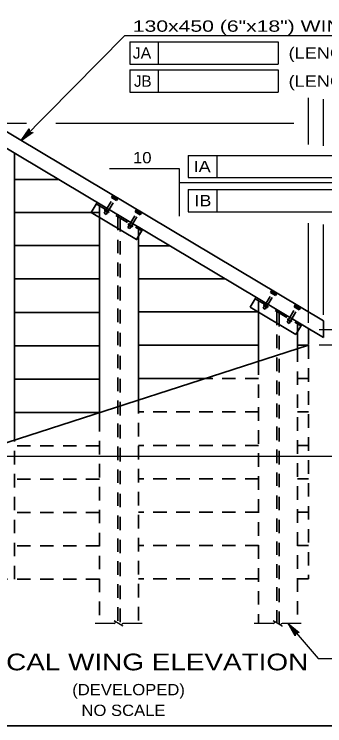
# Model space of a CAD drawing. Extents: x -6.4 to 73.1, y -66 to 0.
# Drawn here: x 50.97 to 54.26, y -43.25 to -35.69 of the extents above; entities that cross this region are included whole.
import ezdxf
from ezdxf.enums import TextEntityAlignment as Align

# ---------------------------------------------------------------- set-up
doc = ezdxf.new("R2010")
doc.units = 0
doc.header["$LTSCALE"] = 0.048
doc.linetypes.add('MEDIUM_DASHED', pattern=[4.5, 3, -1.5])
for name, color, linetype, lineweight in [('1', 7, 'Continuous', 13), ('3', 7, 'Continuous', 35), ('4', 7, 'Continuous', 25), ('5', 7, 'Continuous', 25), ('8', 7, 'Continuous', 25)]:
    doc.layers.add(name, color=color, linetype=linetype, lineweight=lineweight)

msp = doc.modelspace()

# ---------------------------------------------------------------- hatches: boundary and pattern name
at = {"layer": '4'}
for points in [[(51.13325, -36.96742), (51.10633, -36.94083), (51.04017, -37.03475)], [(53.94975, -42.28008), (53.97833, -42.25533), (53.88992, -42.18183)]]:
    msp.add_hatch(color=256, dxfattribs=at).paths.add_polyline_path(points)

# ---------------------------------------------------------------- linework, layer by layer
at = {"layer": '1', "lineweight": 35}
msp.add_lwpolyline([(35.75, -43.25), (67.25, -43.25), (67.25, -22.75), (35.75, -22.75)], close=True, dxfattribs=at)
at = {"layer": '3'}
for p, q in [((50.73242, -36.85133), (54.24933, -38.94825)), ((50.73242, -37.0285), (54.24933, -39.12542)), ((50.96758, -40.21458), (50.96758, -37.16875)), ((51.43492, -37.44733), (50.96758, -37.44733)), ((51.78183, -37.79742), (51.84483, -37.69175)), ((51.78433, -37.79892), (50.96758, -37.79892)), ((51.87142, -37.85083), (51.87142, -39.97992)), ((52.28483, -38.05383), (52.28483, -39.79033)), ((51.87142, -38.1505), (50.96758, -38.1505)), ((52.61533, -38.15117), (52.28483, -38.15117)), ((52.28483, -38.40183), (52.28483, -38.58925)), ((51.87142, -38.50483), (50.96758, -38.50483)), ((53.20508, -38.50275), (52.28483, -38.50275)), ((53.47225, -38.80533), (53.53525, -38.69967)), ((53.47225, -38.80533), (53.95617, -39.09383)), ((51.87142, -38.85917), (50.96758, -38.85917)), ((53.56183, -38.85433), (52.28483, -38.85433)), ((53.56183, -38.85875), (53.56183, -39.37975)), ((53.95617, -39.09383), (54.01917, -38.98817)), ((54.24933, -38.94825), (54.24933, -39.12542)), ((53.97525, -39.06175), (53.97525, -39.24475)), ((54.09333, -39.03242), (54.09333, -39.20142)), ((54.09333, -39.20867), (50.46133, -40.37758)), ((51.87142, -39.2135), (50.96758, -39.2135)), ((53.56183, -39.20867), (52.28483, -39.20867)), ((54.09333, -39.20867), (53.97525, -39.20867)), ((51.87142, -39.56783), (50.96758, -39.56783)), ((52.99242, -39.563), (52.28483, -39.563)), ((51.87142, -39.92217), (50.96758, -39.92217))]:
    msp.add_line(p, q, dxfattribs=at)
at = {"layer": '3', "linetype": 'MEDIUM_DASHED'}
for p, q in [((51.99733, -37.63892), (52.01192, -37.61417)), ((52.00525, -37.64367), (52.01175, -37.63283)), ((52.01808, -37.632), (52.04692, -37.649)), ((51.92067, -37.806), (52.01367, -37.64858)), ((51.94192, -37.81842), (52.03492, -37.66108)), ((52.05125, -37.67075), (51.99733, -37.63892)), ((52.02075, -37.63833), (52.01442, -37.649)), ((52.03975, -37.64942), (52.03342, -37.66025)), ((52.04333, -37.66608), (52.04958, -37.65517)), ((52.05125, -37.67075), (52.06583, -37.64608)), ((51.93383, -37.76467), (51.92742, -37.7755)), ((51.92983, -37.7815), (51.95867, -37.79842)), ((51.93658, -37.78083), (51.943, -37.77)), ((51.95558, -37.79208), (51.96183, -37.78125)), ((52.24933, -37.79192), (52.26392, -37.76725)), ((51.94192, -37.81842), (51.92067, -37.806)), ((51.97183, -37.787), (51.96533, -37.79783)), ((52.17392, -37.95683), (52.26567, -37.80167)), ((52.19517, -37.96933), (52.28692, -37.81417)), ((52.30333, -37.82383), (52.24933, -37.79192)), ((52.25725, -37.79675), (52.26375, -37.78583)), ((52.27283, -37.79142), (52.26642, -37.802)), ((52.27008, -37.785), (52.29892, -37.80208)), ((52.29183, -37.8025), (52.28542, -37.81325)), ((52.29533, -37.81908), (52.30158, -37.80817)), ((52.30333, -37.82383), (52.31792, -37.79917)), ((52.18708, -37.91558), (52.18067, -37.92642)), ((52.18308, -37.93233), (52.212, -37.94933)), ((52.18983, -37.93175), (52.19625, -37.92092)), ((52.20883, -37.94292), (52.21517, -37.93217)), ((52.19517, -37.96933), (52.17392, -37.95683)), ((52.22517, -37.93783), (52.21858, -37.94875)), ((53.61108, -38.81392), (53.70408, -38.6565)), ((53.63233, -38.82633), (53.72533, -38.669)), ((53.68775, -38.64683), (53.70233, -38.62208)), ((53.74167, -38.67867), (53.68775, -38.64683)), ((53.69567, -38.65158), (53.70217, -38.64075)), ((53.71117, -38.64625), (53.70483, -38.65692)), ((53.7085, -38.63992), (53.73733, -38.65692)), ((53.73017, -38.65733), (53.72383, -38.66817)), ((53.73375, -38.674), (53.74, -38.66308)), ((53.74167, -38.67867), (53.75625, -38.654)), ((53.63233, -38.82633), (53.61108, -38.81392)), ((53.62425, -38.77258), (53.61783, -38.78342)), ((53.62025, -38.78942), (53.64908, -38.80633)), ((53.627, -38.78875), (53.63342, -38.77792)), ((53.646, -38.8), (53.65225, -38.78917)), ((53.66225, -38.79492), (53.65575, -38.80575)), ((53.86433, -38.96475), (53.95608, -38.80958)), ((53.88558, -38.97725), (53.97733, -38.82208)), ((53.93975, -38.79983), (53.95433, -38.77517)), ((53.99375, -38.83175), (53.93975, -38.79983)), ((53.94767, -38.80467), (53.95417, -38.79375)), ((53.96325, -38.79933), (53.95683, -38.80992)), ((53.9605, -38.79292), (53.98933, -38.81)), ((53.98225, -38.81042), (53.97583, -38.82117)), ((53.98575, -38.827), (53.992, -38.81608)), ((53.99375, -38.83175), (54.00833, -38.80708)), ((53.88558, -38.97725), (53.86433, -38.96475)), ((53.8775, -38.9235), (53.87108, -38.93433)), ((53.8735, -38.94025), (53.90242, -38.95725)), ((53.88025, -38.93967), (53.88667, -38.92883)), ((53.89925, -38.95083), (53.90558, -38.94008)), ((53.91558, -38.94575), (53.909, -38.95667)), ((54.09333, -39.20867), (54.09333, -41.689)), ((53.97525, -39.242), (53.97525, -42.14725)), ((53.56183, -39.37975), (53.56183, -42.15833)), ((53.56183, -39.563), (52.99242, -39.563)), ((54.09333, -39.563), (53.97525, -39.563)), ((52.28483, -39.79033), (52.28483, -42.14725)), ((53.56183, -39.91733), (52.28483, -39.91733)), ((54.09333, -39.91733), (53.97525, -39.91733)), ((51.87142, -39.97992), (51.87142, -42.15833)), ((50.96758, -41.69383), (50.96758, -40.21458)), ((51.87142, -40.2765), (50.96758, -40.2765)), ((53.56183, -40.27167), (52.28483, -40.27167)), ((54.09333, -40.27167), (53.97525, -40.27167)), ((51.87142, -40.63083), (50.96758, -40.63083)), ((53.56183, -40.626), (52.28483, -40.626)), ((54.09333, -40.626), (53.97525, -40.626)), ((51.87142, -40.98517), (50.96758, -40.98517)), ((53.56183, -40.98033), (52.28483, -40.98033)), ((54.09333, -40.98033), (53.97525, -40.98033)), ((53.56183, -41.33467), (52.28483, -41.33467)), ((54.09333, -41.33467), (53.97525, -41.33467)), ((51.87142, -41.3395), (50.96758, -41.3395)), ((51.87142, -41.69383), (50.58367, -41.69383)), ((53.56183, -41.689), (52.28483, -41.689)), ((54.09333, -41.689), (53.97525, -41.689))]:
    msp.add_line(p, q, dxfattribs=at)
at = {"layer": '3'}
msp.add_lwpolyline([(51.78183, -37.79742), (52.26575, -38.08592), (52.32875, -37.98025)], dxfattribs=at)
at = {"layer": '3', "linetype": 'MEDIUM_DASHED'}
for centre, radius, start, end in [((52.01543, -37.6369), 0.00557, 346.84976, 131.94615), ((52.02341, -37.65552), 0.01754, 20.44796, 98.34796), ((52.04362, -37.65422), 0.00613, 61.22502, 128.11101), ((52.04362, -37.65422), 0.00613, 350.6849, 61.22502), ((51.93285, -37.77677), 0.00557, 166.9183, 312.01468), ((51.95301, -37.77477), 0.01754, 200.51649, 278.41649), ((52.26749, -37.78995), 0.00557, 346.84976, 131.94615), ((51.96162, -37.7931), 0.00613, 170.75344, 237.63943), ((51.96162, -37.7931), 0.00613, 237.63943, 308.17954), ((52.27546, -37.80857), 0.01754, 20.44796, 98.34796), ((52.29567, -37.80726), 0.00613, 61.22502, 128.11101), ((52.29567, -37.80726), 0.00613, 350.6849, 61.22502), ((52.18615, -37.92771), 0.00557, 166.9183, 312.01468), ((52.2063, -37.9257), 0.01754, 200.51649, 278.41649), ((52.21492, -37.94403), 0.00613, 170.75344, 237.63943), ((52.21492, -37.94403), 0.00613, 237.63943, 308.17954), ((53.70585, -38.64482), 0.00557, 346.84976, 131.94615), ((53.71382, -38.66344), 0.01754, 20.44796, 98.34796), ((53.73403, -38.66213), 0.00613, 61.22502, 128.11101), ((53.73403, -38.66213), 0.00613, 350.6849, 61.22502), ((53.62327, -38.78469), 0.00557, 166.9183, 312.01468), ((53.64342, -38.78268), 0.01754, 200.51649, 278.41649), ((53.65203, -38.80101), 0.00613, 170.75344, 237.63943), ((53.65203, -38.80101), 0.00613, 237.63943, 308.17954), ((53.9579, -38.79787), 0.00557, 346.84976, 131.94615), ((53.96588, -38.81649), 0.01754, 20.44796, 98.34796), ((53.98609, -38.81518), 0.00613, 61.22502, 128.11101), ((53.98609, -38.81518), 0.00613, 350.6849, 61.22502), ((53.87657, -38.93562), 0.00557, 166.9183, 312.01468), ((53.89672, -38.93362), 0.01754, 200.51649, 278.41649), ((53.90533, -38.95195), 0.00613, 170.75344, 237.63943), ((53.90533, -38.95195), 0.00613, 237.63943, 308.17954)]:
    msp.add_arc(centre, radius, start, end, dxfattribs=at)
at = {"layer": '4'}
for p, q in [((51.04008, -37.03483), (52.14075, -35.92042)), ((52.14075, -35.92042), (55.88817, -35.92042)), ((52.19292, -35.98667), (53.76775, -35.98667)), ((52.19292, -35.98667), (52.19292, -36.22292)), ((52.49542, -35.98667), (52.49542, -36.22292)), ((53.76775, -35.98667), (53.76775, -36.22292)), ((52.19292, -36.22292), (53.76775, -36.22292)), ((52.19292, -36.28525), (53.76775, -36.28525)), ((52.19292, -36.28525), (52.19292, -36.52142)), ((52.49542, -36.28525), (52.49542, -36.52142)), ((53.76775, -36.28525), (53.76775, -36.52142)), ((52.19292, -36.52142), (53.76775, -36.52142)), ((54.09333, -37.07767), (54.09333, -36.58208)), ((54.24933, -37.09067), (54.24933, -36.59508)), ((50.85417, -36.85125), (51.094, -36.85125)), ((51.40792, -36.85125), (53.93633, -36.85125)), ((52.81467, -37.19217), (54.3895, -37.19217)), ((52.81467, -37.19217), (52.81467, -37.42842)), ((53.11717, -37.19217), (53.11717, -37.42842)), ((52.72075, -37.33667), (51.97742, -37.33667)), ((52.72075, -37.838), (52.72075, -37.33667)), ((52.81467, -37.42842), (54.3895, -37.42842)), ((55.71433, -37.48275), (52.72075, -37.48275)), ((52.81467, -37.55467), (54.3895, -37.55467)), ((52.81467, -37.55467), (52.81467, -37.79092)), ((53.11717, -37.55467), (53.11717, -37.79092)), ((52.81467, -37.79092), (54.3895, -37.79092)), ((54.09333, -38.97092), (54.09333, -37.91233)), ((54.24933, -38.88475), (54.24933, -37.92542)), ((54.20642, -39.04125), (58.26442, -39.04125)), ((54.53533, -39.20867), (54.20392, -39.20867)), ((54.53533, -40.39192), (50.71225, -40.39192)), ((53.87425, -42.16367), (54.19408, -42.53425)), ((54.19408, -42.53425), (57.859, -42.53425))]:
    msp.add_line(p, q, dxfattribs=at)
at = {"layer": '4', "lineweight": 35}
msp.add_line((50.96758, -37.64), (50.96758, -39.64308), dxfattribs=at)
at = {"layer": '4'}
for points in [[(51.04008, -37.03483), (51.125, -36.90908), (51.12258, -36.92283), (51.1255, -36.93408), (51.13142, -36.94233), (51.13975, -36.94817), (51.151, -36.951), (51.16475, -36.94842), (51.04008, -37.03483), (51.151, -36.951), (51.13975, -36.94817), (51.04008, -37.03483), (51.13142, -36.94233), (51.1255, -36.93408), (51.04008, -37.03483), (51.12258, -36.92283)], [(53.87425, -42.16367), (53.99283, -42.25833), (53.97933, -42.25483), (53.96792, -42.25683), (53.95917, -42.26208), (53.95275, -42.26992), (53.949, -42.28092), (53.9505, -42.29483), (53.87425, -42.16367), (53.949, -42.28092), (53.95275, -42.26992), (53.87425, -42.16367), (53.95917, -42.26208), (53.96792, -42.25683), (53.87425, -42.16367), (53.97933, -42.25483)]]:
    msp.add_lwpolyline(points, dxfattribs=at)
for points in [[(51.13325, -36.96742), (51.10633, -36.94083), (51.04017, -37.03475)], [(53.94975, -42.28008), (53.97833, -42.25533), (53.88992, -42.18183)]]:
    msp.add_lwpolyline(points, close=True, dxfattribs=at)
at = {"layer": '8', "linetype": 'MEDIUM_DASHED', "lineweight": 35}
for p, q in [((51.83617, -37.70633), (52.32008, -37.99475)), ((51.87142, -37.72733), (51.87142, -37.85083)), ((51.87142, -37.79892), (51.78433, -37.79892)), ((52.06633, -37.8435), (52.06633, -42.159)), ((52.08992, -37.85758), (52.08992, -42.17383)), ((52.28483, -37.97375), (52.28483, -38.05383)), ((53.52658, -38.71425), (54.0105, -39.00267)), ((53.56183, -38.73525), (53.56183, -38.85875)), ((53.75675, -38.85142), (53.75675, -42.159)), ((53.78033, -38.8655), (53.78033, -42.17383)), ((53.97525, -38.98167), (53.97525, -39.06175))]:
    msp.add_line(p, q, dxfattribs=at)
at = {"layer": '8'}
for p, q in [((52.02758, -42.16367), (51.82367, -42.16367)), ((52.32492, -42.16367), (52.12083, -42.16367)), ((53.71808, -42.16367), (53.51408, -42.16367)), ((54.01533, -42.16367), (53.81133, -42.16367))]:
    msp.add_line(p, q, dxfattribs=at)
for points in [[(52.114, -42.18908), (52.11983, -42.19267), (52.02742, -42.13458), (52.03358, -42.1385)], [(53.8045, -42.18908), (53.81025, -42.19267), (53.71792, -42.13458), (53.72408, -42.1385)]]:
    msp.add_lwpolyline(points, dxfattribs=at)
for centre, start, end in [((52.02637, -42.14998), 275.32859, 57.86724), ((52.12088, -42.1772), 90, 240), ((53.71682, -42.14998), 275.32859, 57.86724), ((53.81133, -42.1772), 90, 240)]:
    msp.add_arc(centre, 0.01364, start, end, dxfattribs=at)

# ---------------------------------------------------------------- texts
at = {"layer": '4'}
for s, height, width, p in [('JA', 0.12, 1.05, (52.32258, -36.16483)), ('TYPICAL WING ELEVATION', 0.1772, 1.25, (52.15475, -42.66108)), ('(DEVELOPED)', 0.12, 1.1, (52.17996, -42.92617)), ('NO SCALE', 0.12, 1.1, (52.12588, -43.14592))]:
    msp.add_text(s, height=height, dxfattribs=dict(at, width=width)).set_placement(p, align=Align.CENTER)
for s, width, p in [('(LENGTH) WINGWALL A', 1.2, (53.88042, -36.16483)), ('(LENGTH) WINGWALL B', 1.2, (53.88042, -36.46342)), ('10', 1.1, (52.22758, -37.27633))]:
    msp.add_text(s, height=0.12, dxfattribs=dict(at, width=width)).set_placement(p)
msp.add_text('JB', height=0.12, dxfattribs=at).set_placement((52.33092, -36.46342), align=Align.CENTER)
at = {"layer": '4', "width": 1.2}
for s, p in [('IA', (52.96131, -37.37036)), ('IB', (52.96973, -37.73285))]:
    msp.add_text(s, height=0.12, rotation=359.938, dxfattribs=at).set_placement(p, align=Align.CENTER)
at = {"layer": '5', "width": 1.4}
msp.add_text('130x450 (6"x18") WING COPING', height=0.12, dxfattribs=at).set_placement((52.22475, -35.87892))

doc.saveas('drawing.dxf')
